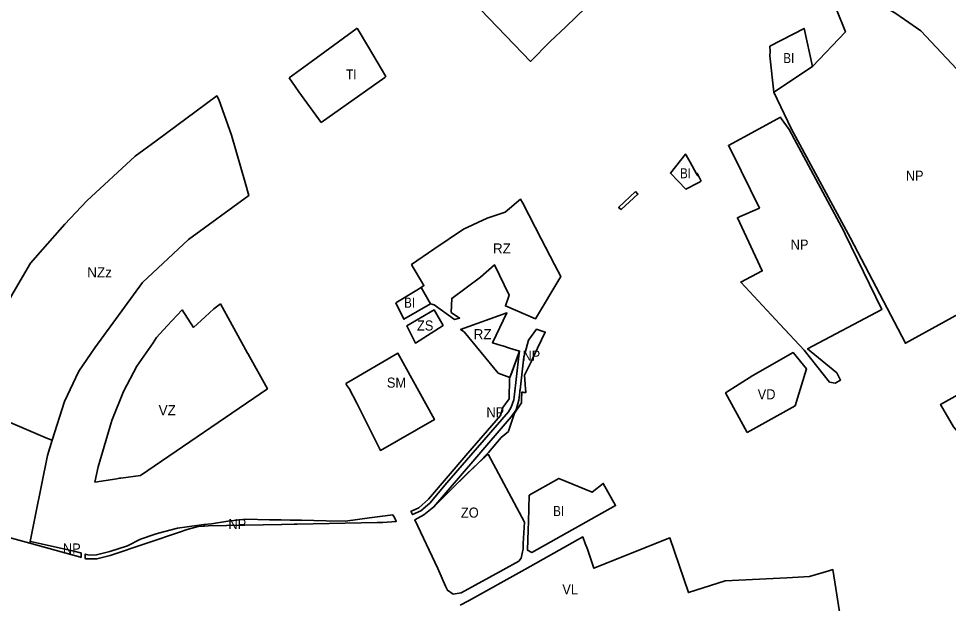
# Model space of a CAD drawing. Extents: x -650276 to -642489, y -1074311 to -1066658.
# Drawn here: x -647227 to -646121, y -1073113 to -1072417 of the extents above; entities that cross this region are included whole.
import ezdxf

# ---------------------------------------------------------------- set-up
doc = ezdxf.new("R2010")
doc.units = 0
doc.header["$LTSCALE"] = 4.8
for name, color, linetype, lineweight in [('18', 7, 'Continuous', 35), ('2', 7, 'Continuous', 35), ('30', 7, 'Continuous', 35), ('34', 7, 'Continuous', 35), ('35', 7, 'Continuous', 35), ('36', 7, 'Continuous', 35), ('41', 7, 'Continuous', 35), ('42', 7, 'Continuous', 35), ('46', 7, 'Continuous', 35), ('48', 7, 'Continuous', 35), ('6', 7, 'Continuous', 35)]:
    doc.layers.add(name, color=color, linetype=linetype, lineweight=lineweight)
doc.layers.add('62', color=7, linetype='Continuous')
doc.layers.add('63', color=7, linetype='Continuous')

msp = doc.modelspace()

# ---------------------------------------------------------------- linework, layer by layer
at = {"layer": '18'}
msp.add_lwpolyline([(-646837.81, -1072851.3), (-646836.5, -1072853.76), (-646833.67, -1072857.15), (-646824.89, -1072874.66), (-646796.68, -1072930.92), (-646732.28, -1072894.29), (-646775.85, -1072815.39), (-646834.08, -1072849.15)], close=True, dxfattribs=at)
at = {"layer": '2'}
msp.add_line((-646417.787, -1072612.168), (-646414.77, -1072610.61), dxfattribs=at)
for points in [[(-646333.34, -1072461.67), (-646328.45, -1072504.81), (-646282.47, -1072474.34), (-646292.44, -1072428.89), (-646333.33, -1072450.12), (-646332.68, -1072456.19)], [(-646778.2, -1072755.19), (-646755.1, -1072741.28), (-646748.3, -1072737.01), (-646737.05, -1072756.4), (-646768.74, -1072774.78)], [(-646620.38, -1073015.9), (-646620.71, -1073025.49), (-646621.44, -1073049.79), (-646616.55, -1073052.21), (-646516.7, -1072996.65), (-646531.46, -1072970.12), (-646544.68, -1072980.62), (-646584.23, -1072964.22), (-646619.48, -1072984.34)]]:
    msp.add_lwpolyline(points, close=True, dxfattribs=at)
for points in [[(-646420.36, -1072601.78), (-646427.95, -1072588.07), (-646432.57, -1072579.75), (-646433.36, -1072578.45), (-646451.458, -1072601.008), (-646433.024, -1072620.04), (-646417.787, -1072612.168)], [(-646414.77, -1072610.61), (-646419.11, -1072602.03), (-646419.47, -1072601.31), (-646419.02, -1072604.18), (-646420.36, -1072601.78)]]:
    msp.add_lwpolyline(points, dxfattribs=at)
at = {"layer": '30'}
for points in [[(-646824.42, -1072428.58), (-646878.91, -1072468.54), (-646905.18, -1072487.8)], [(-646867.283, -1072540.984), (-646791.569, -1072487.198), (-646790.354, -1072486.136), (-646810.77, -1072451.09), (-646824.42, -1072428.58)], [(-646905.18, -1072487.8), (-646898.1, -1072498.02), (-646893.64, -1072504.45), (-646867.283, -1072540.984)]]:
    msp.add_lwpolyline(points, dxfattribs=at)
at = {"layer": '34'}
msp.add_lwpolyline([(-646247.76, -1073138.19), (-646258.14, -1073072.71), (-646262.94, -1073074.15), (-646285.77, -1073081.01), (-646312.87, -1073082.4), (-646386.27, -1073086.15), (-646430.02, -1073100.1), (-646452.08, -1073034.96), (-646542.62, -1073071.1), (-646550.01, -1073048.55), (-646552.79, -1073041.53), (-646555.79, -1073033.92), (-646624.69, -1073072.66), (-646691.76, -1073109.71), (-646701.78, -1073114.9)], dxfattribs=at)
at = {"layer": '35'}
msp.add_lwpolyline([(-646360.22, -1072909.57), (-646303.02, -1072877.74), (-646289.63, -1072834.04), (-646305.56, -1072814.43), (-646353.25, -1072841.63), (-646385.86, -1072862.59)], close=True, dxfattribs=at)
at = {"layer": '36'}
for points in [[(-646987.154, -1072756.377), (-646995.02, -1072762.45), (-647005.249, -1072771.938), (-647019.06, -1072784.57), (-647032.7, -1072763.68), (-647050.492, -1072782.771)], [(-646954.7, -1072815.232), (-646957.105, -1072810.92), (-646987.154, -1072756.377)], [(-647050.492, -1072782.771), (-647063.04, -1072796.74), (-647067.22, -1072802.77), (-647086.65, -1072830.76), (-647102.38, -1072860.7), (-647116.33, -1072895.3)], [(-647136.39, -1072968.63), (-647110.32, -1072964.56), (-647107.01, -1072964.04), (-647105.4, -1072963.84), (-647082.36, -1072960.95), (-646931.1, -1072857.55), (-646954.51, -1072815.63), (-646954.7, -1072815.232)], [(-647116.33, -1072895.3), (-647132.47, -1072950.4), (-647136.39, -1072968.63)]]:
    msp.add_lwpolyline(points, dxfattribs=at)
at = {"layer": '41'}
msp.add_lwpolyline([(-646756.92, -1072799.26), (-646754.96, -1072803.29), (-646722.072, -1072782.236), (-646732.76, -1072763.81), (-646765, -1072782.52)], close=True, dxfattribs=at)
at = {"layer": '42'}
msp.add_lwpolyline([(-646696.83, -1072385.81), (-646618.158, -1072468.098), (-646594.606, -1072444.422), (-646575.792, -1072426.789), (-646504.244, -1072357.026)], dxfattribs=at)
msp.add_lwpolyline([(-646668.53, -1072935.52), (-646680.07, -1072945.74), (-646710.3, -1072975.31), (-646732.95, -1072998.07), (-646744.92, -1073007.46), (-646755.58, -1073013.43), (-646728.25, -1073071.54), (-646719.09, -1073092.43), (-646716.98, -1073097.26), (-646709.88, -1073101.87), (-646700.42, -1073100.42), (-646650.54, -1073072.96), (-646631.82, -1073062.65), (-646629.15, -1073059.18), (-646626.91, -1073048.17), (-646626.55, -1073041.48), (-646625.01, -1073016.38)], close=True, dxfattribs=at)
at = {"layer": '46'}
msp.add_lwpolyline([(-647284.75, -1072877.79), (-647282.31, -1072878.82), (-647192.718, -1072916.582), (-647187.445, -1072918.804), (-647172.48, -1072872.92), (-647155.72, -1072836.46), (-647136.69, -1072808.98), (-647079.74, -1072731.1), (-647025.04, -1072679.96), (-646953.2, -1072627.45), (-646957.5, -1072612.09), (-646973.68, -1072555.68), (-646989.01, -1072513.62), (-646991.24, -1072509.24), (-647063.38, -1072562.42), (-647088.397, -1072580.865), (-647088.4, -1072580.868), (-647146.21, -1072634.02), (-647172.36, -1072661.69), (-647198.77, -1072691.71), (-647212.92, -1072708.05), (-647236.54, -1072748.09), (-647252.29, -1072783.24), (-647263.58, -1072809.97)], close=True, dxfattribs=at)
at = {"layer": '48'}
msp.add_line((-646779.55, -1073011.68), (-646781.703, -1073007.452), dxfattribs=at)
for points in [[(-646110.61, -1072477.49), (-646153.49, -1072431.54), (-646172.81, -1072418.2), (-646184.449, -1072410.256), (-646194.19, -1072404.62), (-646254.75, -1072404.25), (-646243.17, -1072432.88), (-646282.47, -1072474.34), (-646328.45, -1072504.81), (-646307.6, -1072547.74), (-646236.97, -1072678.31), (-646171.72, -1072803.51), (-646052.58, -1072737.82)], [(-646781.703, -1073007.452), (-646809.778, -1073011.019), (-646838.25, -1073014.938), (-646861.07, -1073014.672), (-646890.523, -1073014.073), (-646904.131, -1073013.793), (-646914.796, -1073013.573), (-646918.156, -1073013.511)], [(-646800.44, -1073016.74), (-646793.8, -1073016.61), (-646777.74, -1073015.29), (-646779.55, -1073011.68)], [(-646918.156, -1073013.511), (-646928.807, -1073013.313), (-646956.919, -1073012.775), (-646978.077, -1073014.931), (-646997.824, -1073018.092), (-647006.715, -1073019.236), (-647006.15, -1073020.99), (-647001.66, -1073020.72), (-646914.54, -1073019)], [(-646914.54, -1073019), (-646913.94, -1073018.99), (-646899.22, -1073018.7), (-646895.76, -1073018.63), (-646800.44, -1073016.74)]]:
    msp.add_lwpolyline(points, dxfattribs=at)
for points in [[(-646310.01, -1072549.22), (-646319.56, -1072536.05), (-646320.62, -1072534.6), (-646350.18, -1072550.59), (-646382.41, -1072568.01), (-646377.84, -1072576.29), (-646345.6, -1072642.55), (-646368.51, -1072652.81), (-646371.66, -1072654.2), (-646342.08, -1072717.43), (-646367.72, -1072730.68), (-646321.171, -1072780.535), (-646292.17, -1072811.6), (-646261.97, -1072849.66), (-646255.39, -1072850.83), (-646249.04, -1072847.16), (-646253.56, -1072838.8), (-646288.27, -1072810.22), (-646199.72, -1072763.1), (-646243.32, -1072673.57), (-646245.13, -1072670.2), (-646278.44, -1072608.07)], [(-646493.229, -1072622.74), (-646513.209, -1072641.935), (-646510.28, -1072644.42), (-646490.11, -1072626.15)], [(-646644.059, -1072908.208), (-646637.2, -1072886.57), (-646628.7, -1072874.5), (-646628.58, -1072869.88), (-646628.36, -1072861.71), (-646627.159, -1072861.792), (-646625.96, -1072861.874), (-646625.3, -1072861.919), (-646624.824, -1072861.951), (-646623.67, -1072862.024), (-646623.712, -1072861.37), (-646623.95, -1072857.6), (-646625.02, -1072841.21), (-646618.521, -1072827.719), (-646617.407, -1072825.407), (-646614.07, -1072818.47), (-646600.37, -1072790.04), (-646603.99, -1072788.901), (-646610.86, -1072786.74), (-646620.27, -1072799.95), (-646624.54, -1072814.52), (-646625.91, -1072819.66), (-646630.45, -1072858.93), (-646630.57, -1072859.99), (-646630.76, -1072861.61), (-646631.89, -1072871.33), (-646635.11, -1072882.47), (-646640.96, -1072890.83), (-646684.36, -1072941.43), (-646732.95, -1072998.07), (-646710.3, -1072975.31), (-646693.9, -1072958.84), (-646680.07, -1072945.74), (-646668.09, -1072933.43), (-646652.76, -1072915.66), (-646644.069, -1072908.218), (-646644.061, -1072908.209)], [(-645993.47, -1072818.44), (-645991.37, -1072798.84), (-645996.8, -1072801.88), (-646129.91, -1072876.24), (-646114.5, -1072902.8), (-646089.39, -1072931.92), (-646062.04, -1072943.58), (-646053.287, -1072942.399), (-646017.65, -1072937.59), (-646019.21, -1072926.91), (-646021.64, -1072901.6), (-646012.37, -1072860.3)], [(-646642.438, -1072844.29), (-646642.939, -1072845.68), (-646643.574, -1072869.57), (-646650.798, -1072879.828), (-646653.846, -1072889.44), (-646692.432, -1072934.135), (-646739.241, -1072988.798), (-646751.061, -1072999.106), (-646758.883, -1073002.885), (-646760.416, -1073003.25), (-646758.44, -1073007.19), (-646748.51, -1073002.74), (-646737.7, -1072993.52), (-646717.7, -1072969.5), (-646689.13, -1072936.62), (-646644.12, -1072884.84), (-646640.92, -1072879.6), (-646637.92, -1072870.91), (-646637.52, -1072867.43), (-646631.85, -1072818.45), (-646631.08, -1072812.68), (-646640.313, -1072838.394), (-646642.404, -1072844.195), (-646642.39, -1072844.2)], [(-647293.317, -1072873.549), (-647293.351, -1072873.533), (-647331.82, -1072854.49), (-647375.92, -1072833.99), (-647387.64, -1072868.69), (-647392.96, -1072918.277), (-647394.87, -1072936.08), (-647388.62, -1072948.03), (-647395.47, -1072993.25), (-647367.45, -1073002.47), (-647353.78, -1073003.1), (-647213.99, -1073041.449), (-647210.396, -1073023.593), (-647207.176, -1073007.598), (-647192.93, -1072936.82), (-647187.445, -1072918.804), (-647192.718, -1072916.582), (-647282.31, -1072878.82), (-647284.75, -1072877.79)], [(-647006.715, -1073019.236), (-647009.402, -1073019.582), (-647026.763, -1073021.811), (-647037.971, -1073023.24), (-647060.677, -1073029.351), (-647064.784, -1073030.747), (-647082.267, -1073036.684), (-647097.466, -1073044.268), (-647118.513, -1073051.327), (-647134.596, -1073054.974), (-647143.312, -1073055.421), (-647147.85, -1073054.204), (-647147.91, -1073059.64), (-647147.43, -1073059.78), (-647147.17, -1073059.97), (-647134.03, -1073059.94), (-647118.27, -1073055.88), (-647033.44, -1073027.43), (-647028.91, -1073025.91), (-647026.54, -1073025.11), (-647013.4, -1073021.42), (-647006.15, -1073020.99)], [(-647152.621, -1073052.925), (-647154.999, -1073052.287), (-647161.068, -1073050.946), (-647161.068, -1073050.946), (-647161.068, -1073050.946), (-647213.218, -1073039.42), (-647213.562, -1073039.322), (-647213.99, -1073041.449), (-647153.44, -1073058.06), (-647152.96, -1073058.19)]]:
    msp.add_lwpolyline(points, close=True, dxfattribs=at)
at = {"layer": '6'}
for points in [[(-646737.05, -1072756.4), (-646732.5, -1072757.63), (-646708.65, -1072775.02), (-646702.45, -1072773.39), (-646712.46, -1072766.76), (-646711.79, -1072750.02), (-646677.39, -1072724.85), (-646660.89, -1072709.97), (-646643.36, -1072746.04), (-646647.93, -1072759.01), (-646612.11, -1072774.56), (-646581.92, -1072723.91), (-646589.37, -1072709.83), (-646605.23, -1072679.37), (-646627.32, -1072636.95), (-646629.86, -1072632.07), (-646648.27, -1072647.48), (-646669.6, -1072654.53), (-646697.89, -1072667.65)], [(-646697.89, -1072667.65), (-646732.95, -1072691.68), (-646759.491, -1072709.878), (-646757.5, -1072713.3), (-646747.87, -1072729.85), (-646744.94, -1072734.88), (-646748.3, -1072737.01), (-646737.05, -1072756.4)], [(-646653.02, -1072806.07), (-646663.07, -1072803.04), (-646663.07, -1072803.04), (-646646.12, -1072767.32), (-646646.31, -1072767.388), (-646701.12, -1072787.08), (-646697.09, -1072790.03), (-646656.36, -1072839.08)], [(-646656.36, -1072839.08), (-646642.404, -1072844.195), (-646631.08, -1072812.68), (-646643.01, -1072809.08), (-646651.11, -1072806.64), (-646653.02, -1072806.07)]]:
    msp.add_lwpolyline(points, dxfattribs=at)

# ---------------------------------------------------------------- texts
at = {"layer": '62'}
for s, width, p in [('BI', 0.85, (-646317, -1072470.167)), ('TI', 0.85, (-646837.377, -1072489.619)), ('BI', 0.85, (-646440, -1072607.167)), ('NP', 0.95, (-646171.335, -1072610.048)), ('NP', 0.95, (-646308.335, -1072692.048)), ('BI', 0.85, (-646768.325, -1072761.133)), ('ZS', 0.95, (-646753.085, -1072788.28)), ('NP', 0.95, (-646627.575, -1072824.064)), ('SM', 0.95, (-646788.938, -1072856.245)), ('VD', 0.95, (-646347.605, -1072870.155)), ('NP', 0.95, (-646670.505, -1072891.594)), ('ZO', 0.95, (-646700.791, -1073010.902)), ('BI', 0.85, (-646590.991, -1073009.043)), ('NP', 0.95, (-646977.505, -1073024.594)), ('NP', 0.95, (-647174.505, -1073053.594)), ('VL', 0.95, (-646580.107, -1073102.218))]:
    msp.add_text(s, height=12, dxfattribs=dict(at, width=width)).set_placement(p)
for s, p in [('RZ', (-646662.725, -1072696.633)), ('NZz', (-647145.58, -1072725.109)), ('RZ', (-646685.725, -1072798.633))]:
    msp.add_text(s, height=12, dxfattribs=at).set_placement(p)
at = {"layer": '63'}
msp.add_text('VZ', height=12, dxfattribs=at).set_placement((-647060.598, -1072889.069))

doc.saveas('drawing.dxf')
